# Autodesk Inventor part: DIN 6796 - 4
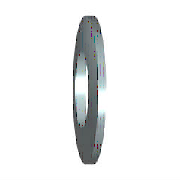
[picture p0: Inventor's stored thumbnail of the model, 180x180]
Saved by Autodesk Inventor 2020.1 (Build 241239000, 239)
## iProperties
Created: 2019-01
Part Number: DIN 6796 - 4
Material: Steel, Mild
Description: Conical Spring Washer
Document SubType Name: Modeling
Standard: DIN 6796
Designer: Safarabadi
Standard Revision: 2009-08
Standards Organization: DIN
Language: en-US
Size Designation: 4
Categories: <MemberInstance><Categories><Category DisplayName="Fasteners" InternalName="e4da775c-781d-43d5-af7c-5136215cf5a6" Mnemonic="FSTN"><Category DisplayName="Washers
Density: 7.85 g/cm^3
Appearance: Semi-Polished
IsCustomPart: 1
Author: Safarabadi
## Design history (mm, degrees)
revolve "IDS_BODY" stored, may be unused: angle "d13" = 90 deg
body "Solid1"
workaxis "Work Axis1"
workplane "Work Plane1"
sketch "Sketch"
  geometry: L1 (-4.5, 0)-(-4.5, 1.009); L2 (-4.5, 1.009)-(-2.28, 1.3); L3 (-2.28, 1.3)-(-2.15, 0.309); L4 (-4.5, 0)-(-2.15, 0.309); L5 (0, 0)-(0, 8.521)
  constraints: 10 end point, 2 perpendicular, 2 vertical, 1 horizontal alignment
  dimensions: "d8" = 4.5 distance from line of L5.start L1 (= 0.5 x SD2); "d10" = 2.15 horizontal distance of L5.start L3.end (= 0.5 x SD1); "d11" = 1.3 vertical distance of L5.start L2.end (= SH); "d12" = 1 distance between parallel lines of L4 L2 (= SD)
other parameters: "SD1" = 4.3 [user parameter; used in 1 equation term], "SD2" = 9 [user parameter; used in 1 equation term], "SD" = 1 [user parameter; used in 1 equation term], "d6" = 0, "SH" = 1.3 [user parameter; used in 1 equation term], "d14" = 0, "d15" = 0, "d17" = 0, "d18" = 0, "NND" = 4 [user parameter]
